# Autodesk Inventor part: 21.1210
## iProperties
Created: 2006-02
Part Number: 21.1210
Material: Steel, Mild
Description: M8 x 40 SHCS
Document SubType Name: Modeling
Standard: DIN 7984
Designer: Andy Moles
Standards Organization: DIN
Language: en-US
Size Designation: M8 x 40
Categories: <MemberInstance><Categories><Category DisplayName="Fasteners" InternalName="e4da775c-781d-43d5-af7c-5136215cf5a6" Mnemonic="FSTN"><Category DisplayName="Bolts"
Density: 7.86 g/cm^3
Mass: 20.1648 g
Surface Area: 15.2032 cm^2
Volume: 2.56549 cm^3
Vendor: S
Author: Andy Moles
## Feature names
1. Body [Revolution]
2. Slot [Extrusion]
3. Fillet1
4. Chamfer1
